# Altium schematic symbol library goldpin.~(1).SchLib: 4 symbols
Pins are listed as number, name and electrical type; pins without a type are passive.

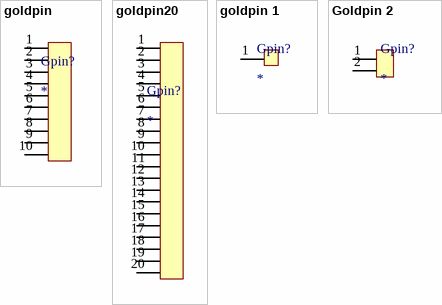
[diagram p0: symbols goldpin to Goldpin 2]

## goldpin
designator Gpin?
footprint goldpin 10
pins: 1, 2, 3, 4, 5, 6, 7, 8, 9, 10

## goldpin20
designator Gpin?
footprint PCBComponent_1
pins: 1, 2, 3, 4, 5, 6, 7, 8, 9, 10, 11 1, 12, 13 3, 14 4, 15 5, 16 6, 17 7, 18 8, 19 9, 20 10

## goldpin 1
designator Gpin?
footprint GOLDPIN 1
pins: 1

## Goldpin 2
designator Gpin?
footprint Goldpin 2
pins: 1, 2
